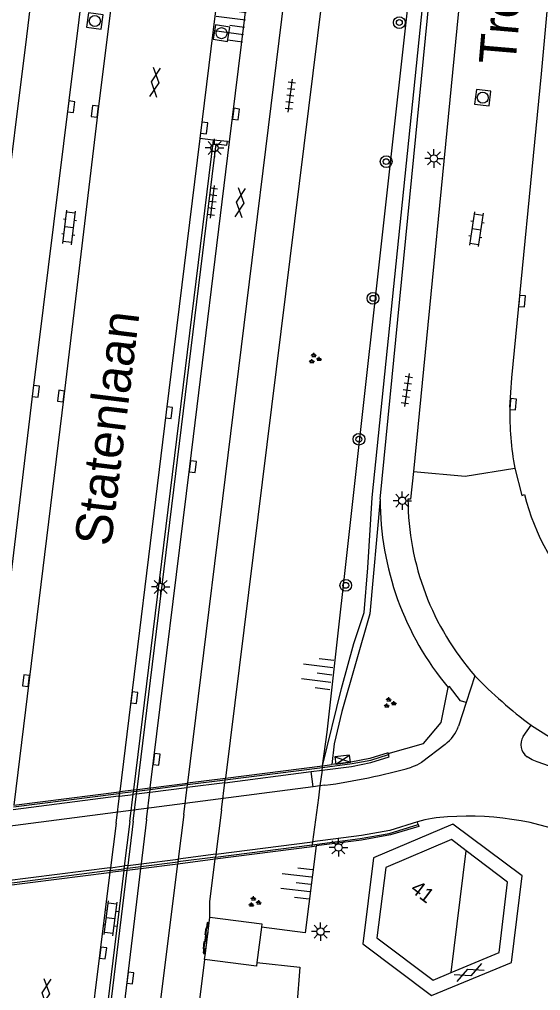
# Model space of a CAD drawing. Extents: x 131000 to 133014, y 396499 to 399001.
# Drawn here: x 131707.6 to 131743, y 397413.3 to 397479.3 of the extents above; entities that cross this region are included whole.
import ezdxf

# ---------------------------------------------------------------- set-up
doc = ezdxf.new("R2010")
doc.units = 0
for name, color, linetype in [('gg-afsc-hekwerk', 7, 'Continuous'), ('gg-afsc-muur', 7, 'Continuous'), ('gg-anno-huisnummerreeks BGT', 7, 'Continuous'), ('gg-anno-openbare ruimte label', 7, 'Continuous'), ('gg-bbg-bijgebouw', 7, 'Continuous'), ('gg-bbg-hoofdgebouw', 7, 'Continuous'), ('gg-bbg-luifel en loopbrug', 7, 'Continuous'), ('gg-knt-BGT kruinlijn', 7, 'Continuous'), ('gg-knt-verharding', 7, 'Continuous'), ('gg-knt-verharding niveau 01', 7, 'Continuous'), ('gg-knt-verharding nz', 7, 'Continuous'), ('gg-kwrk-keermuur', 7, 'Continuous'), ('gg-kwrk-kunstwerk', 7, 'Continuous'), ('gg-kwrk-kunstwerk niveau 01', 7, 'Continuous'), ('gt-grn-afwateringsgoot', 7, 'Continuous'), ('gt-grn-groengrens', 7, 'Continuous'), ('gt-grn-vlakafsluiter', 7, 'Continuous'), ('gt-symb-afwateringsgoot', 7, 'Continuous'), ('gt-symb-boom', 7, 'Continuous'), ('gt-symb-gesloten verharding', 7, 'Continuous'), ('gt-symb-groenvak', 7, 'Continuous'), ('gt-symb-kast', 7, 'Continuous'), ('gt-symb-klinker verharding', 7, 'Continuous'), ('gt-symb-kolk', 7, 'Continuous'), ('gt-symb-lichtmast', 7, 'Continuous'), ('gt-symb-rioolschacht', 7, 'Continuous'), ('gt-symb-talud symbool', 7, 'Continuous'), ('gt-symb-tegel verharding', 7, 'Continuous')]:
    doc.layers.add(name, color=color, linetype=linetype)

# ---------------------------------------------------------------- blocks, each defined once
blk = doc.blocks.new('gt0-KL1')
at = {"layer": 'gt-symb-klinker verharding'}
for p, q in [((-1.15, 0.3), (1.15, 0.3)), ((-1, -0.3), (-1, 0.3)), ((-0.5, 0.3), (-0.5, 0.45)), ((0, -0.3), (0, 0.3)), ((0.5, 0.3), (0.5, 0.45)), ((1, -0.3), (1, 0.3)), ((-1.15, -0.3), (1.15, -0.3)), ((-0.5, -0.45), (-0.5, -0.3)), ((0.5, -0.45), (0.5, -0.3))]:
    blk.add_line(p, q, dxfattribs=at)
blk = doc.blocks.new('gt0-RS')
at = {"layer": 'gt-symb-rioolschacht'}
blk.add_lwpolyline([(-0.5, -0.5), (0.5, -0.5), (0.5, 0.5), (-0.5, 0.5)], close=True, dxfattribs=at)
blk.add_circle((0, 0), 0.375, dxfattribs=at)
blk = doc.blocks.new('gt0-KOLK')
at = {"layer": 'gt-symb-kolk'}
blk.add_lwpolyline([(0, 0), (0.375, 0), (0.375, 0.4), (-0.375, 0.4), (-0.375, 0), (0, 0)], dxfattribs=at)
blk = doc.blocks.new('gt0-TEG1')
at = {"layer": 'gt-symb-tegel verharding'}
for p, q in [((-1.125, 0), (1.125, 0)), ((-0.9, -0.25), (-0.9, 0.25)), ((-0.45, -0.25), (-0.45, 0.25)), ((0, -0.25), (0, 0.25)), ((0.45, -0.25), (0.45, 0.25)), ((0.9, -0.25), (0.9, 0.25))]:
    blk.add_line(p, q, dxfattribs=at)
blk = doc.blocks.new('gt0-LMAST')
at = {"layer": 'gt-symb-lichtmast'}
for p, q in [((-0.182, 0.173), (-0.447, 0.438)), ((-0.005, 0.246), (-0.005, 0.621)), ((0.172, 0.173), (0.437, 0.438)), ((-0.255, -0.004), (-0.63, -0.004)), ((-0.182, -0.181), (-0.447, -0.446)), ((-0.005, -0.254), (-0.005, -0.629)), ((0.437, -0.446), (0.172, -0.181)), ((0.245, -0.004), (0.62, -0.004))]:
    blk.add_line(p, q, dxfattribs=at)
blk.add_circle((-0.005, -0.004), 0.25, dxfattribs=at)
blk = doc.blocks.new('gt0-GESVH1')
at = {"layer": 'gt-symb-gesloten verharding'}
for p, q in [((-0.992, -0.261), (0.008, 0.239)), ((0.008, -0.261), (-0.992, 0.239)), ((0.008, 0.239), (1.008, -0.261)), ((1.008, 0.239), (0.008, -0.261))]:
    blk.add_line(p, q, dxfattribs=at)
blk = doc.blocks.new('gt0-GRVAK')
at = {"layer": 'gt-symb-groenvak'}
for p, q in [((-0.11, 0.189), (-0.228, 0.24)), ((-0.182, 0.153), (0.088, 0.153)), ((-0.091, 0.211), (-0.156, 0.322)), ((-0.047, 0.214), (-0.047, 0.393)), ((-0.004, 0.211), (0.061, 0.322)), ((0.015, 0.189), (0.133, 0.24)), ((0.262, -0.052), (0.197, 0.059)), ((0.305, -0.049), (0.305, 0.13)), ((0.349, -0.052), (0.414, 0.059)), ((-0.245, -0.228), (-0.363, -0.177)), ((-0.318, -0.264), (-0.047, -0.264)), ((-0.226, -0.206), (-0.291, -0.095)), ((-0.183, -0.203), (-0.183, -0.024)), ((-0.139, -0.206), (-0.074, -0.095)), ((-0.12, -0.228), (-0.002, -0.177)), ((0.243, -0.074), (0.125, -0.023)), ((0.17, -0.11), (0.441, -0.11)), ((0.368, -0.074), (0.486, -0.023))]:
    blk.add_line(p, q, dxfattribs=at)
blk = doc.blocks.new('gt0-BOOM')
at = {"layer": 'gt-symb-boom'}
for radius in [0.4, 0.2]:
    blk.add_circle((0, 0), radius, dxfattribs=at)
blk = doc.blocks.new('gt0-KAST')
at = {"layer": 'gt-symb-kast'}
for p, q in [((-0.501, -0.249), (0.501, 0.249)), ((-0.501, 0.249), (0.501, -0.249))]:
    blk.add_line(p, q, dxfattribs=at)
blk.add_lwpolyline([(0.501, 0.249), (-0.501, 0.249), (-0.501, -0.249), (0.501, -0.249)], close=True, dxfattribs=at)
blk = doc.blocks.new('gt0-TALUD_1')
at = {"layer": 'gt-symb-talud symbool'}
for p, q in [((0, -1), (0, 0)), ((-1, -1), (-1, 0)), ((-0.5, -2), (-0.5, 0)), ((0.5, -2), (0.5, 0)), ((1, -1), (1, 0))]:
    blk.add_line(p, q, dxfattribs=at)
blk = doc.blocks.new('gt0-AFWGT_1')
at = {"layer": 'gt-symb-afwateringsgoot'}
for p, q in [((-1.076, 0), (-0.726, 0)), ((-0.225, 0), (0.225, 0)), ((0.725, 0), (1.075, 0))]:
    blk.add_line(p, q, dxfattribs=at)
for points in [[(-0.726, 0.075), (-0.225, 0.075), (-0.225, -0.075), (-0.726, -0.075)], [(0.225, 0.075), (0.725, 0.075), (0.725, -0.075), (0.225, -0.075)]]:
    blk.add_lwpolyline(points, close=True, dxfattribs=at)

msp = doc.modelspace()

# ---------------------------------------------------------------- linework, layer by layer
at = {"layer": 'gg-afsc-hekwerk'}
for p, q in [((131721.607, 397427.656), (131728.215, 397428.5)), ((131719.036, 397427.327), (131721.607, 397427.656)), ((131715.605, 397426.889), (131716.498, 397427.002)), ((131716.498, 397427.002), (131719.036, 397427.327)), ((131707.212, 397425.815), (131714.376, 397426.731)), ((131714.376, 397426.731), (131714.431, 397426.738)), ((131714.431, 397426.738), (131715.365, 397426.858)), ((131715.365, 397426.858), (131715.605, 397426.889)), ((131720.947, 397422.404), (131727.523, 397423.242)), ((131720.947, 397422.404), (131718.39, 397422.077)), ((131714.963, 397421.641), (131715.866, 397421.755)), ((131715.866, 397421.755), (131718.39, 397422.077)), ((131713.788, 397421.491), (131706.571, 397420.571)), ((131713.788, 397421.491), (131714.723, 397421.61)), ((131714.963, 397421.641), (131714.723, 397421.61))]:
    msp.add_line(p, q, dxfattribs=at)
for points in [[(131728.215, 397428.5), (131730.23, 397428.758), (131731.514, 397428.999), (131732.707, 397429.379)], [(131727.523, 397423.242), (131730.789, 397423.658), (131732.742, 397424.014), (131734.723, 397424.625)]]:
    msp.add_lwpolyline(points, dxfattribs=at)
at = {"layer": 'gg-afsc-muur'}
for p, q in [((131720.782, 397471.12), (131715.379, 397426.97)), ((131721.75, 397471.013), (131720.782, 397471.12)), ((131715.379, 397426.97), (131715.365, 397426.858)), ((131715.605, 397426.889), (131715.619, 397427.001)), ((131715.115, 397424.819), (131715.365, 397426.858)), ((131715.356, 397424.85), (131715.605, 397426.889)), ((131715.115, 397424.819), (131714.723, 397421.61)), ((131715.356, 397424.85), (131714.963, 397421.641)), ((131714.708, 397421.488), (131712.611, 397404.357)), ((131712.841, 397404.301), (131714.948, 397421.519)), ((131714.723, 397421.61), (131714.708, 397421.488)), ((131714.948, 397421.519), (131714.963, 397421.641))]:
    msp.add_line(p, q, dxfattribs=at)
msp.add_lwpolyline([(131715.619, 397427.001), (131720.987, 397470.864), (131721.725, 397470.774), (131721.75, 397471.013)], dxfattribs=at)
at = {"layer": 'gg-bbg-bijgebouw'}
for p, q in [((131720.254, 397415.876), (131720.515, 397417.929)), ((131720.515, 397417.929), (131720.566, 397418.326)), ((131724.061, 397417.636), (131723.759, 397415.236)), ((131720.2, 397415.449), (131720.254, 397415.876))]:
    msp.add_line(p, q, dxfattribs=at)
for points in [[(131720.566, 397418.326), (131724.09, 397417.869), (131724.061, 397417.636)], [(131723.759, 397415.236), (131723.729, 397414.999), (131720.2, 397415.449)]]:
    msp.add_lwpolyline(points, dxfattribs=at)
at = {"layer": 'gg-bbg-hoofdgebouw'}
msp.add_line((131736.971, 397414.559), (131737.98, 397422.838), dxfattribs=at)
msp.add_lwpolyline([(131737.98, 397422.838), (131736.98, 397423.6), (131732.52, 397421.7), (131731.91, 397416.92), (131735.74, 397414.05), (131736.971, 397414.559)], dxfattribs=at)
at = {"layer": 'gg-bbg-luifel en loopbrug'}
msp.add_lwpolyline([(131736.971, 397414.559), (131740.24, 397415.91), (131740.8, 397420.69), (131737.98, 397422.838)], dxfattribs=at)
at = {"layer": 'gg-knt-BGT kruinlijn'}
msp.add_line((131727.785, 397423.16), (131727.051, 397417.248), dxfattribs=at)
msp.add_lwpolyline([(131728.229, 397428.607), (131728.53, 397430.9), (131734.35, 397483.23), (131733.34, 397485.9), (131734.67, 397508.32), (131734.908, 397522.597)], dxfattribs=at)
at = {"layer": 'gg-knt-verharding'}
for p, q in [((131732.091, 397533.377), (131719.05, 397427.438)), ((131733.422, 397522.887), (131721.621, 397427.765)), ((131732.135, 397446.718), (131737.373, 397500)), ((131739.445, 397500), (131734.411, 397448.6)), ((131720.782, 397471.12), (131719.883, 397471.219)), ((131738.583, 397434.715), (131737.987, 397432.895)), ((131737.987, 397432.895), (131737.465, 397431.3)), ((131741.86, 397430.585), (131742.399, 397431.361)), ((131742.399, 397431.361), (131742.424, 397431.341)), ((131728.381, 397427.279), (131728.048, 397427.235)), ((131716.096, 397403.5), (131718.375, 397421.956)), ((131720.566, 397419.371), (131720.932, 397422.284)), ((131715.852, 397421.635), (131713.726, 397404.083)), ((131720.566, 397418.326), (131720.566, 397419.371)), ((131720.2, 397415.449), (131719.8, 397412.16)), ((131726.672, 397414.918), (131726.47, 397412.304))]:
    msp.add_line(p, q, dxfattribs=at)
for points in [[(131728.131, 397618.539), (131726.176, 397597.967), (131725.659, 397593.768), (131724.86, 397586.761), (131715.855, 397513.103), (131708.532, 397454.074), (131706.19, 397434.727), (131705.054, 397425.654)], [(131730.563, 397618.311), (131729.687, 397612.789), (131728.434, 397603.929), (131727.574, 397597.673), (131725.848, 397582.285), (131725.291, 397577.081), (131724.28, 397566.115), (131724.064, 397563.12), (131722.374, 397549.466), (131717.77, 397511.74), (131712.944, 397473.041), (131710.636, 397453.695), (131707.226, 397425.93)], [(131728.713, 397543.343), (131727.32, 397531.778), (131719.883, 397471.219)], [(131721.904, 397470.996), (131728.382, 397523.57), (131729.784, 397535.131), (131729.999, 397536.537), (131730.045, 397536.755)], [(131740.962, 397452.964), (131741.081, 397454.971), (131743.11, 397475.613), (131744.057, 397486.134), (131745.464, 397500)], [(131719.883, 397471.219), (131717.586, 397452.621), (131714.445, 397426.851)], [(131716.511, 397427.114), (131719.205, 397448.947), (131721.904, 397470.996)], [(131734.411, 397448.6), (131737.912, 397448.276), (131741.306, 397448.817)], [(131741.306, 397448.817), (131741.767, 397446.981), (131741.956, 397447.034)], [(131734.411, 397448.6), (131734.208, 397446.715), (131734.027, 397446.723)], [(131732.692, 397429.436), (131735.09, 397430.122), (131736.296, 397431.545), (131736.766, 397433.918)], [(131742.424, 397431.341), (131746.284, 397428.918), (131749.252, 397427.354), (131751.494, 397426.349), (131758.491, 397423.692), (131758.572, 397423.853)], [(131736.555, 397430.062), (131734.955, 397428.835), (131734.623, 397428.639), (131734.264, 397428.508)], [(131746.619, 397427.546), (131742.823, 397428.867), (131742.466, 397429.016), (131742.134, 397429.22)], [(131741.8, 397421.13), (131737.08, 397424.63), (131731.68, 397422.35), (131730.97, 397416.51), (131735.64, 397412.99), (131741.08, 397415.25), (131741.8, 397421.13)], [(131711.693, 397404.584), (131713.103, 397415.907), (131713.773, 397421.369)]]:
    msp.add_lwpolyline(points, dxfattribs=at)
for centre, radius, start, end in [((131759.439, 397452.409), 18.485, 178.27918, 191.20466), ((131756.219, 397450.472), 14.672, 193.55146, 226.57569), ((131752.109, 397446.707), 19.974, 179.96822, 219.81171), ((131752.323, 397446.796), 18.296, 180.22982, 221.32505), ((131761.96, 397457.464), 32.619, 224.22024, 233.15329), ((131734.901, 397432.231), 2.728, 307.32323, 340.04079), ((131742.693, 397430.042), 0.994, 146.89565, 235.80493), ((131722.5, 397470.125), 43.247, 277.81544, 285.78414), ((131737.001, 397416.996), 8.137, 91.93782, 106.66162), ((131738.161, 397405.099), 20.081, 65.50516, 94.09804)]:
    msp.add_arc(centre, radius, start, end, dxfattribs=at)
at = {"layer": 'gg-knt-verharding niveau 01'}
for p, q in [((131727.583, 397427.173), (131727.451, 397428.207)), ((131727.583, 397427.173), (131682.745, 397421.383)), ((131728.048, 397427.235), (131727.583, 397427.173))]:
    msp.add_line(p, q, dxfattribs=at)
at = {"layer": 'gg-knt-verharding nz'}
for p, q in [((131721.351, 397425.619), (131721.607, 397427.656)), ((131721.607, 397427.656), (131721.621, 397427.765)), ((131716.252, 397424.965), (131716.498, 397427.002)), ((131716.511, 397427.114), (131716.498, 397427.002)), ((131718.785, 397425.289), (131719.036, 397427.327)), ((131719.05, 397427.438), (131719.036, 397427.327)), ((131714.181, 397424.699), (131714.431, 397426.738)), ((131714.431, 397426.738), (131714.445, 397426.851)), ((131716.252, 397424.965), (131715.866, 397421.755)), ((131718.785, 397425.289), (131718.39, 397422.077)), ((131721.351, 397425.619), (131720.947, 397422.404)), ((131714.181, 397424.699), (131713.788, 397421.491)), ((131720.932, 397422.284), (131720.947, 397422.404)), ((131715.866, 397421.755), (131715.852, 397421.635)), ((131718.39, 397422.077), (131718.375, 397421.956)), ((131713.773, 397421.369), (131713.788, 397421.491))]:
    msp.add_line(p, q, dxfattribs=at)
for points in [[(131725.307, 397625.043), (131723.475, 397605.413), (131708.104, 397478.147), (131701.447, 397425.078)], [(131737.987, 397432.895), (131737.605, 397433.019), (131736.855, 397433.987), (131736.766, 397433.918)]]:
    msp.add_lwpolyline(points, dxfattribs=at)
at = {"layer": 'gg-kwrk-keermuur'}
for p, q in [((131727.051, 397417.248), (131724.061, 397417.636)), ((131723.759, 397415.236), (131726.672, 397414.918))]:
    msp.add_line(p, q, dxfattribs=at)
at = {"layer": 'gg-kwrk-kunstwerk'}
for p, q in [((131732.692, 397429.436), (131732.707, 397429.379)), ((131728.229, 397428.607), (131728.854, 397428.687)), ((131734.723, 397424.625), (131734.668, 397424.792)), ((131727.507, 397423.125), (131727.785, 397423.16))]:
    msp.add_line(p, q, dxfattribs=at)
for points in [[(131728.189, 397428.301), (131730.189, 397428.556), (131731.503, 397428.82), (131732.752, 397429.213), (131732.707, 397429.379)], [(131732.692, 397429.436), (131732.677, 397429.491), (131731.431, 397429.102), (131730.144, 397428.851), (131728.854, 397428.687)], [(131734.668, 397424.792), (131732.787, 397424.209), (131730.872, 397423.859), (131727.548, 397423.433)], [(131734.723, 397424.625), (131734.768, 397424.488), (131732.841, 397423.92), (131730.882, 397423.56), (131727.785, 397423.16)]]:
    msp.add_lwpolyline(points, dxfattribs=at)
at = {"layer": 'gg-kwrk-kunstwerk niveau 01'}
for p, q in [((131721.621, 397427.765), (131728.229, 397428.607)), ((131727.451, 397428.207), (131728.189, 397428.301)), ((131728.189, 397428.301), (131728.048, 397427.235)), ((131728.189, 397428.301), (131728.215, 397428.5)), ((131728.215, 397428.5), (131728.229, 397428.607)), ((131719.05, 397427.438), (131721.621, 397427.765)), ((131721.582, 397427.458), (131727.451, 397428.207)), ((131714.445, 397426.851), (131715.379, 397426.97)), ((131715.379, 397426.97), (131715.619, 397427.001)), ((131715.619, 397427.001), (131716.511, 397427.114)), ((131716.505, 397426.811), (131719, 397427.129)), ((131716.511, 397427.114), (131716.543, 397427.118)), ((131716.543, 397427.118), (131719.038, 397427.436)), ((131719.012, 397427.131), (131719, 397427.129)), ((131721.582, 397427.458), (131719.012, 397427.131)), ((131719.038, 397427.436), (131719.05, 397427.438)), ((131728.048, 397427.235), (131727.943, 397426.44)), ((131714.352, 397426.536), (131707.188, 397425.622)), ((131707.226, 397425.93), (131714.389, 397426.844)), ((131714.352, 397426.536), (131714.407, 397426.543)), ((131714.389, 397426.844), (131714.445, 397426.851)), ((131714.407, 397426.543), (131715.341, 397426.662)), ((131715.581, 397426.693), (131715.341, 397426.662)), ((131715.581, 397426.693), (131716.474, 397426.807)), ((131716.474, 397426.807), (131716.505, 397426.811)), ((131727.943, 397426.44), (131727.548, 397423.433)), ((131720.932, 397422.284), (131727.507, 397423.125)), ((131720.971, 397422.593), (131727.548, 397423.433)), ((131727.507, 397423.125), (131727.523, 397423.242)), ((131727.548, 397423.433), (131727.523, 397423.242)), ((131720.971, 397422.593), (131718.413, 397422.266)), ((131713.751, 397421.672), (131706.594, 397420.757)), ((131713.751, 397421.672), (131713.811, 397421.68)), ((131713.811, 397421.68), (131714.746, 397421.798)), ((131714.986, 397421.829), (131714.746, 397421.798)), ((131714.986, 397421.829), (131715.889, 397421.944)), ((131715.864, 397421.637), (131718.375, 397421.956)), ((131715.889, 397421.944), (131715.902, 397421.946)), ((131715.902, 397421.946), (131718.402, 397422.265)), ((131718.375, 397421.956), (131720.932, 397422.284)), ((131718.413, 397422.266), (131718.402, 397422.265)), ((131706.556, 397420.446), (131713.713, 397421.361)), ((131713.713, 397421.361), (131713.773, 397421.369)), ((131713.773, 397421.369), (131714.708, 397421.488)), ((131714.708, 397421.488), (131714.948, 397421.519)), ((131714.948, 397421.519), (131715.852, 397421.635)), ((131715.852, 397421.635), (131715.864, 397421.637))]:
    msp.add_line(p, q, dxfattribs=at)
at = {"layer": 'gt-grn-afwateringsgoot'}
msp.add_lwpolyline([(131720.515, 397417.929), (131720.367, 397417.948), (131720.105, 397415.894), (131720.254, 397415.876)], dxfattribs=at)
at = {"layer": 'gt-grn-groengrens'}
for points in [[(131728.229, 397428.607), (131729.501, 397433.852), (131730.344, 397436.914), (131731.046, 397439.017), (131731.309, 397442.063), (131731.589, 397446.827), (131735.908, 397488.753), (131736.958, 397500.067), (131738.399, 397515.189), (131739.093, 397522.139)], [(131732.135, 397446.718), (131731.439, 397438.938), (131729.533, 397432.295), (131729.009, 397430.105), (131728.854, 397428.687)]]:
    msp.add_lwpolyline(points, dxfattribs=at)
at = {"layer": 'gt-grn-vlakafsluiter'}
msp.add_line((131721.75, 397471.013), (131721.904, 397470.996), dxfattribs=at)

# ---------------------------------------------------------------- block references
at = {"layer": 'gt-symb-afwateringsgoot', "xscale": 1.0000331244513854, "yscale": 1.0000331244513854, "rotation": -97.26714512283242}
msp.add_blockref('gt0-AFWGT_1', (131720.288, 397416.878), dxfattribs=at)
at = {"layer": 'gt-symb-boom'}
for p in [(131733.443, 397479.1), (131732.549, 397469.654), (131731.652, 397460.363), (131730.697, 397450.792), (131729.802, 397440.866)]:
    msp.add_blockref('gt0-BOOM', p, dxfattribs=at)
at = {"layer": 'gt-symb-gesloten verharding'}
for p, rotation in [((131716.826, 397475.036), 82.99574075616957), ((131722.611, 397466.857), 82.99574075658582), ((131738.19, 397414.57), 22.589003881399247), ((131709.388, 397413.133), 82.93185994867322)]:
    msp.add_blockref('gt0-GESVH1', p, dxfattribs=dict(at, rotation=rotation))
at = {"layer": 'gt-symb-groenvak'}
for p in [(131727.68, 397456.267), (131732.768, 397432.873), (131723.575, 397419.346)]:
    msp.add_blockref('gt0-GRVAK', p, dxfattribs=at)
at = {"layer": 'gt-symb-kast', "rotation": 6.81873712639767}
msp.add_blockref('gt0-KAST', (131729.585, 397429.032), dxfattribs=at)
at = {"layer": 'gt-symb-klinker verharding'}
for p, rotation in [((131710.993, 397465.187), 83.10945167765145), ((131738.683, 397465.066), -98.45426172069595), ((131713.813, 397418.242), 82.81812146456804)]:
    msp.add_blockref('gt0-KL1', p, dxfattribs=dict(at, rotation=rotation))
at = {"layer": 'gt-symb-kolk'}
for p, rotation in [((131710.935, 397473.402), -97.06814005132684), ((131712.944, 397473.041), 83.22321716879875), ((131722.138, 397472.904), -97.00425924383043), ((131719.975, 397471.963), -97.00425924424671), ((131741.583, 397460.19), -95.51097695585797), ((131708.532, 397454.074), -96.89054832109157), ((131710.636, 397453.695), 82.99574075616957), ((131740.984, 397453.191), -95.56802405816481), ((131717.586, 397452.621), -97.06814005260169), ((131719.205, 397448.947), -96.94741065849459), ((131708.256, 397434.361), 83.05258934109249), ((131715.23, 397433.255), -96.94741065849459), ((131716.747, 397429.072), -97.06814005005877), ((131713.103, 397415.907), -97.12501635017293), ((131714.956, 397414.204), -96.89054832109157)]:
    msp.add_blockref('gt0-KOLK', p, dxfattribs=dict(at, rotation=rotation))
at = {"layer": 'gt-symb-lichtmast'}
for p in [(131720.883, 397470.583), (131735.796, 397469.87), (131733.647, 397446.62), (131717.221, 397440.767), (131729.311, 397423.063), (131728.095, 397417.342)]:
    msp.add_blockref('gt0-LMAST', p, dxfattribs=at)
at = {"layer": 'gt-symb-rioolschacht'}
for p, rotation in [((131712.742, 397479.207), 82.41293092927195), ((131721.354, 397478.381), 170.55652508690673), ((131739.116, 397473.997), -97.18187853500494)]:
    msp.add_blockref('gt0-RS', p, dxfattribs=dict(at, rotation=rotation))
at = {"layer": 'gt-symb-talud symbool'}
for p, xscale, yscale, rotation in [((131722.91, 397478.79), 1.0004818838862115, 1.0004818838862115, -97.46597406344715), ((131728.849, 397434.781), 0.99962092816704, 0.9996209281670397, -97.5302533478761), ((131727.421, 397420.559), 1.000178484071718, 1.000178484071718, -96.37182240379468)]:
    msp.add_blockref('gt0-TALUD_1', p, dxfattribs=dict(at, xscale=xscale, yscale=yscale, rotation=rotation))
at = {"layer": 'gt-symb-tegel verharding'}
for p, rotation in [((131726.032, 397474.13), 82.99574075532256), ((131720.733, 397466.921), 82.93185994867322), ((131733.951, 397454.139), -98.45426172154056)]:
    msp.add_blockref('gt0-TEG1', p, dxfattribs=dict(at, rotation=rotation))

# ---------------------------------------------------------------- texts
at = {"layer": 'gg-anno-huisnummerreeks BGT'}
msp.add_text('41', height=1, rotation=322.7, dxfattribs=at).set_placement((131734.134, 397420.109))
at = {"layer": 'gg-anno-openbare ruimte label'}
for s, rotation, p in [('Troelstrastraat', 85.1, (131741.332, 397476.169)), ('Statenlaan', 83, (131713.831, 397443.459))]:
    msp.add_text(s, height=2.5, rotation=rotation, dxfattribs=at).set_placement(p)

doc.saveas('drawing.dxf')
